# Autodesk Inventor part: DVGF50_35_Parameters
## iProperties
Created: 2010-04
Part Number: DVGF50_35_Parameters
Document SubType Name: Modeling
Designer: TB
Density: 1 g/cm^3
Slaglengde: 100.000 mm
Vinkel_Plussport: 0.00 deg
Vinkel_Minusport: 0.00 deg
Forlengelse_rør: 0.000 mm
Author: TB
